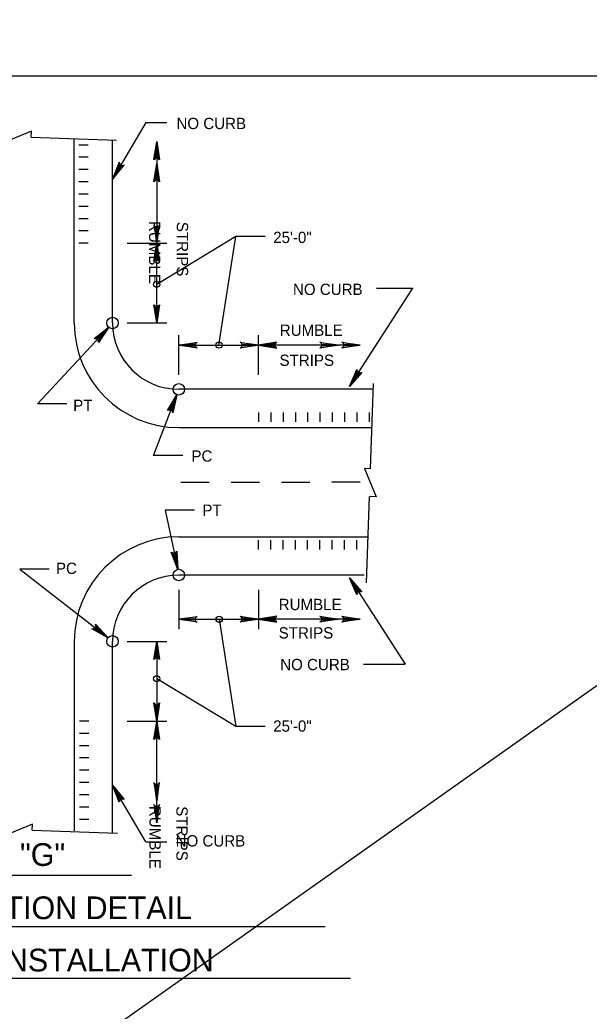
# Model space of a CAD drawing. Extents: x 632008 to 634206, y 294231 to 297795.
# Drawn here: x 633738.6 to 633889.8, y 295155.4 to 295418.6 of the extents above; entities that cross this region are included whole.
import ezdxf

# ---------------------------------------------------------------- set-up
doc = ezdxf.new("R2010")
doc.units = 0
for name, color, linetype in [('1', 7, 'Continuous'), ('2', 7, 'Continuous'), ('3', 7, 'Continuous'), ('Level 2', 7, 'Continuous')]:
    doc.layers.add(name, color=color, linetype=linetype)

msp = doc.modelspace()

# ---------------------------------------------------------------- linework, layer by layer
at = {"layer": '1'}
for p, q in [((633753.07, 295338.13), (633753.07, 295387.09)), ((633763.23, 295338.13), (633763.23, 295386.54)), ((633756.79, 295385.38), (633754.27, 295385.38)), ((633756.79, 295382.12), (633754.27, 295382.12)), ((633756.79, 295378.86), (633754.27, 295378.86)), ((633756.79, 295375.6), (633754.27, 295375.6)), ((633756.79, 295372.34), (633754.27, 295372.34)), ((633756.79, 295369.08), (633754.27, 295369.08)), ((633756.79, 295365.82), (633754.27, 295365.82)), ((633756.79, 295362.56), (633754.27, 295362.56)), ((633795.96, 295361.09), (633774.96, 295348.37)), ((633791.5, 295332.25), (633795.96, 295361.09)), ((633756.79, 295359.29), (633754.27, 295359.29)), ((633832.49, 295320.52), (633780.84, 295320.52)), ((633802, 295314.39), (633802, 295311.88)), ((633805.27, 295314.39), (633805.27, 295311.88)), ((633808.53, 295314.39), (633808.53, 295311.88)), ((633811.79, 295314.39), (633811.79, 295311.88)), ((633815.05, 295314.39), (633815.05, 295311.88)), ((633818.31, 295314.39), (633818.31, 295311.88)), ((633821.57, 295314.39), (633821.57, 295311.88)), ((633824.83, 295314.39), (633824.83, 295311.88)), ((633828.1, 295314.39), (633828.1, 295311.88)), ((633831.36, 295314.39), (633831.36, 295311.88)), ((633780.84, 295310.36), (633832.13, 295310.36)), ((633780.84, 295281.37), (633831.12, 295281.37)), ((633802, 295277.96), (633802, 295280.48)), ((633805.27, 295277.96), (633805.27, 295280.48)), ((633808.53, 295277.96), (633808.53, 295280.48)), ((633811.79, 295277.96), (633811.79, 295280.48)), ((633815.05, 295277.96), (633815.05, 295280.48)), ((633818.31, 295277.96), (633818.31, 295280.48)), ((633821.57, 295277.96), (633821.57, 295280.48)), ((633824.83, 295277.96), (633824.83, 295280.48)), ((633828.1, 295277.96), (633828.1, 295280.48)), ((633830.05, 295271.21), (633780.84, 295271.21)), ((633791.55, 295259.48), (633795.96, 295230.97)), ((633753.07, 295253.6), (633753.07, 295203.27)), ((633763.23, 295202.72), (633763.23, 295253.6)), ((633795.96, 295230.97), (633774.96, 295243.69)), ((633756.97, 295232.44), (633754.45, 295232.44)), ((633756.97, 295229.18), (633754.45, 295229.18)), ((633756.97, 295225.91), (633754.45, 295225.91)), ((633756.97, 295222.65), (633754.45, 295222.65)), ((633756.97, 295219.39), (633754.45, 295219.39)), ((633756.97, 295216.13), (633754.45, 295216.13)), ((633756.97, 295212.87), (633754.45, 295212.87)), ((633756.97, 295209.61), (633754.45, 295209.61)), ((633756.97, 295206.35), (633754.45, 295206.35)), ((633705.11, 295191.51), (633768.25, 295191.51))]:
    msp.add_line(p, q, dxfattribs=at)
msp.add_lwpolyline([(634127.07, 294839.62), (634127.07, 295403.62), (633341.07, 295403.62), (633341.07, 294839.62), (634127.07, 294839.62), (634127.07, 294865.98), (633927.07, 294865.98), (633927.07, 294930.66), (634127.07, 294930.66), (634127.07, 294959.62), (633927.07, 294959.62), (633927.07, 294839.62), (634005.87, 294839.62), (634005.87, 294865.98), (634005.87, 294839.62), (634082.87, 294839.62), (634082.87, 294865.98), (634082.87, 294853.66), (634127.07, 294853.66)], dxfattribs=at)
msp.add_lwpolyline([(634127.07, 294839.62), (634127.07, 295403.62), (633341.07, 295403.62), (633341.07, 294839.62), (634127.07, 294839.62), (634127.07, 294865.98), (633927.07, 294865.98), (633927.07, 294930.66), (634127.07, 294930.66), (634127.07, 294959.62), (633927.07, 294959.62), (633927.07, 294839.62), (634005.87, 294839.62), (634005.87, 294865.98), (634005.87, 294839.62), (634082.87, 294839.62), (634082.87, 294865.98), (634082.87, 294853.66), (634127.07, 294853.66)], dxfattribs=at)
msp.add_lwpolyline([(634127.07, 294839.62), (634127.07, 295403.62), (633341.07, 295403.62), (633341.07, 294839.62), (634127.07, 294839.62), (634127.07, 294865.98), (633927.07, 294865.98), (633927.07, 294930.66), (634127.07, 294930.66), (634127.07, 294959.62), (633927.07, 294959.62), (633927.07, 294839.62), (634005.87, 294839.62), (634005.87, 294865.98), (634005.87, 294839.62), (634082.87, 294839.62), (634082.87, 294865.98), (634082.87, 294853.66), (634127.07, 294853.66)], dxfattribs=at)
msp.add_lwpolyline([(634127.07, 294839.62), (634127.07, 295403.62), (633341.07, 295403.62), (633341.07, 294839.62), (634127.07, 294839.62), (634127.07, 294865.98), (633927.07, 294865.98), (633927.07, 294930.66), (634127.07, 294930.66), (634127.07, 294959.62), (633927.07, 294959.62), (633927.07, 294839.62), (634005.87, 294839.62), (634005.87, 294865.98), (634005.87, 294839.62), (634082.87, 294839.62), (634082.87, 294865.98), (634082.87, 294853.66), (634127.07, 294853.66)], dxfattribs=at)
msp.add_lwpolyline([(634127.07, 294839.62), (634127.07, 295403.62), (633341.07, 295403.62), (633341.07, 294839.62), (634127.07, 294839.62), (634127.07, 294865.98), (633927.07, 294865.98), (633927.07, 294930.66), (634127.07, 294930.66), (634127.07, 294959.62), (633927.07, 294959.62), (633927.07, 294839.62), (634005.87, 294839.62), (634005.87, 294865.98), (634005.87, 294839.62), (634082.87, 294839.62), (634082.87, 294865.98), (634082.87, 294853.66), (634127.07, 294853.66)], dxfattribs=at)
for centre in [(633774.96, 295348.37), (633791.5, 295332.25), (633791.55, 295259.48), (633774.96, 295243.69)]:
    msp.add_circle(centre, 0.821, dxfattribs=at)
for centre, radius, start, end in [((633780.84, 295338.13), 27.77, 180, 270), ((633780.84, 295338.13), 17.61, 180, 270), ((633780.84, 295253.6), 27.77, 90, 180), ((633780.84, 295253.6), 17.61, 90, 180)]:
    msp.add_arc(centre, radius, start, end, dxfattribs=at)
at = {"layer": '2'}
for p, q in [((633741.71, 295389.09), (633734.21, 295385.95)), ((633741.65, 295387.49), (633741.71, 295389.09)), ((633741.65, 295387.49), (633764.26, 295386.7)), ((633831.75, 295299.45), (633832.54, 295322.06)), ((633830.15, 295299.51), (633833.29, 295292.01)), ((633831.75, 295299.45), (633830.15, 295299.51)), ((633830.69, 295269.12), (633831.49, 295292.07)), ((633833.29, 295292.01), (633831.69, 295292.07)), ((633741.97, 295205.07), (633734.47, 295201.93)), ((633741.91, 295203.47), (633741.97, 295205.07)), ((633741.91, 295203.47), (633764.52, 295202.68)), ((633656.2, 295177.87), (633819.72, 295177.87)), ((633648.82, 295164.16), (633826.43, 295164.16))]:
    msp.add_line(p, q, dxfattribs=at)
at = {"layer": '3'}
for p, q in [((633772.04, 295391.33), (633763.23, 295376.28)), ((633772.04, 295391.33), (633777.67, 295391.33)), ((633774.96, 295386.28), (633774.96, 295359.29)), ((633803.76, 295361.09), (633795.96, 295361.09)), ((633767.12, 295359.29), (633777.67, 295359.29)), ((633774.96, 295338.13), (633774.96, 295359.29)), ((633826.15, 295321.3), (633842.97, 295347.34)), ((633833.36, 295347.34), (633842.97, 295347.34)), ((633762.2, 295337.02), (633743.27, 295316.67)), ((633767.12, 295338.13), (633777.67, 295338.13)), ((633780.84, 295324.41), (633780.84, 295334.9)), ((633802, 295324.41), (633802, 295334.9)), ((633780.84, 295332.25), (633802, 295332.25)), ((633828.99, 295332.25), (633802, 295332.25)), ((633774.1, 295302.91), (633780.3, 295319.1)), ((633751.08, 295316.67), (633743.27, 295316.67)), ((633781.9, 295302.91), (633774.1, 295302.91)), ((633781.37, 295295.87), (633788.91, 295295.87)), ((633794.73, 295295.87), (633802.27, 295295.87)), ((633808.09, 295295.87), (633815.63, 295295.87)), ((633828.99, 295295.87), (633821.45, 295295.87)), ((633777.18, 295288.44), (633780.53, 295272.7)), ((633784.98, 295288.44), (633777.18, 295288.44)), ((633738.63, 295272.78), (633762.03, 295254.53)), ((633746.43, 295272.78), (633738.63, 295272.78)), ((633826.15, 295270.43), (633840.91, 295247.57)), ((633780.84, 295267.32), (633780.84, 295256.83)), ((633802, 295267.32), (633802, 295256.83)), ((633780.84, 295259.48), (633802, 295259.48)), ((633828.99, 295259.48), (633802, 295259.48)), ((633767.12, 295253.6), (633777.67, 295253.6)), ((633774.96, 295253.6), (633774.96, 295232.44)), ((633829.92, 295247.57), (633840.91, 295247.57)), ((633767.12, 295232.44), (633777.67, 295232.44)), ((633774.96, 295205.45), (633774.96, 295232.44)), ((633803.76, 295230.97), (633795.96, 295230.97)), ((633772.04, 295200.4), (633763.23, 295215.45)), ((633772.04, 295200.4), (633777.67, 295200.4))]:
    msp.add_line(p, q, dxfattribs=at)
for points in [[(633774.38, 295381.67), (633774.72, 295381.85), (633774.96, 295386.28), (633774.38, 295381.67), (633774.18, 295381.44), (633774.96, 295386.28), (633775.18, 295381.85), (633775.51, 295381.69), (633774.96, 295386.28), (633775.73, 295381.44), (633775.51, 295381.69)], [(633765.06, 295380.55), (633765.26, 295380.23), (633763.23, 295376.28), (633765.06, 295380.55), (633765, 295380.85), (633763.23, 295376.28), (633765.66, 295379.99), (633766.02, 295379.97), (633763.23, 295376.28), (633766.34, 295380.07), (633766.02, 295379.97)], [(633774.38, 295375.85), (633774.72, 295376.02), (633774.96, 295380.46), (633774.38, 295375.85), (633774.18, 295375.61), (633774.96, 295380.46), (633775.18, 295376.03), (633775.51, 295375.86), (633774.96, 295380.46), (633775.73, 295375.61), (633775.51, 295375.86)], [(633774.38, 295363.9), (633774.72, 295363.73), (633774.96, 295359.29), (633774.38, 295363.9), (633774.18, 295364.14), (633774.96, 295359.29), (633775.18, 295363.73), (633775.51, 295363.89), (633774.96, 295359.29), (633775.73, 295364.14), (633775.51, 295363.89)], [(633774.38, 295354.69), (633774.72, 295354.86), (633774.96, 295359.29), (633774.38, 295354.69), (633774.18, 295354.45), (633774.96, 295359.29), (633775.18, 295354.86), (633775.51, 295354.7), (633774.96, 295359.29), (633775.73, 295354.45), (633775.51, 295354.7)], [(633775.54, 295342.74), (633775.2, 295342.57), (633774.96, 295338.13), (633775.54, 295342.74), (633775.74, 295342.98), (633774.96, 295338.13), (633774.74, 295342.56), (633774.41, 295342.72), (633774.96, 295338.13), (633774.19, 295342.98), (633774.41, 295342.72)], [(633758.64, 295334.04), (633759, 295333.94), (633762.2, 295337.02), (633758.64, 295334.04), (633758.33, 295334.01), (633762.2, 295337.02), (633759.34, 295333.63), (633759.47, 295333.28), (633762.2, 295337.02), (633759.46, 295332.95), (633759.47, 295333.28)], [(633785.45, 295331.67), (633785.28, 295332), (633780.84, 295332.25), (633785.45, 295331.67), (633785.69, 295331.47), (633780.84, 295332.25), (633785.28, 295332.47), (633785.44, 295332.8), (633780.84, 295332.25), (633785.69, 295333.02), (633785.44, 295332.8)], [(633797.4, 295332.83), (633797.57, 295332.49), (633802, 295332.25), (633797.4, 295332.83), (633797.16, 295333.03), (633802, 295332.25), (633797.57, 295332.03), (633797.41, 295331.7), (633802, 295332.25), (633797.16, 295331.48), (633797.41, 295331.7)], [(633806.61, 295332.83), (633806.44, 295332.49), (633802, 295332.25), (633806.61, 295332.83), (633806.85, 295333.03), (633802, 295332.25), (633806.44, 295332.03), (633806.6, 295331.7), (633802, 295332.25), (633806.85, 295331.48), (633806.6, 295331.7)], [(633818.56, 295332.83), (633818.73, 295332.49), (633823.17, 295332.25), (633818.56, 295332.83), (633818.32, 295333.03), (633823.17, 295332.25), (633818.74, 295332.03), (633818.57, 295331.7), (633823.17, 295332.25), (633818.32, 295331.48), (633818.57, 295331.7)], [(633824.38, 295332.83), (633824.56, 295332.49), (633828.99, 295332.25), (633824.38, 295332.83), (633824.15, 295333.03), (633828.99, 295332.25), (633824.56, 295332.03), (633824.4, 295331.7), (633828.99, 295332.25), (633824.15, 295331.48), (633824.4, 295331.7)], [(633829.13, 295324.86), (633828.76, 295324.9), (633826.15, 295321.3), (633829.13, 295324.86), (633829.43, 295324.95), (633826.15, 295321.3), (633828.37, 295325.14), (633828.18, 295325.46), (633826.15, 295321.3), (633828.13, 295325.79), (633828.18, 295325.46)], [(633778.11, 295315.01), (633778.48, 295315.05), (633780.3, 295319.1), (633778.11, 295315.01), (633777.84, 295314.86), (633780.3, 295319.1), (633778.92, 295314.89), (633779.17, 295314.62), (633780.3, 295319.1), (633779.28, 295314.31), (633779.17, 295314.62)], [(633780.13, 295277.32), (633779.84, 295277.08), (633780.53, 295272.7), (633780.13, 295277.32), (633780.28, 295277.59), (633780.53, 295272.7), (633779.39, 295276.98), (633779.03, 295277.07), (633780.53, 295272.7), (633778.76, 295277.27), (633779.03, 295277.07)], [(633828.16, 295266.25), (633828.35, 295266.57), (633826.15, 295270.43), (633828.16, 295266.25), (633828.12, 295265.94), (633826.15, 295270.43), (633828.74, 295266.83), (633829.1, 295266.87), (633826.15, 295270.43), (633829.42, 295266.78), (633829.1, 295266.87)], [(633785.45, 295258.9), (633785.28, 295259.24), (633780.84, 295259.48), (633785.45, 295258.9), (633785.69, 295258.7), (633780.84, 295259.48), (633785.28, 295259.7), (633785.44, 295260.03), (633780.84, 295259.48), (633785.69, 295260.25), (633785.44, 295260.03)], [(633797.4, 295260.06), (633797.57, 295259.73), (633802, 295259.48), (633797.4, 295260.06), (633797.16, 295260.26), (633802, 295259.48), (633797.57, 295259.26), (633797.41, 295258.93), (633802, 295259.48), (633797.16, 295258.71), (633797.41, 295258.93)], [(633806.61, 295260.06), (633806.44, 295259.73), (633802, 295259.48), (633806.61, 295260.06), (633806.85, 295260.26), (633802, 295259.48), (633806.44, 295259.26), (633806.6, 295258.93), (633802, 295259.48), (633806.85, 295258.71), (633806.6, 295258.93)], [(633818.56, 295260.06), (633818.73, 295259.73), (633823.17, 295259.48), (633818.56, 295260.06), (633818.32, 295260.26), (633823.17, 295259.48), (633818.74, 295259.26), (633818.57, 295258.93), (633823.17, 295259.48), (633818.32, 295258.71), (633818.57, 295258.93)], [(633824.38, 295260.06), (633824.56, 295259.73), (633828.99, 295259.48), (633824.38, 295260.06), (633824.15, 295260.26), (633828.99, 295259.48), (633824.56, 295259.26), (633824.4, 295258.93), (633828.99, 295259.48), (633824.15, 295258.71), (633824.4, 295258.93)], [(633758.76, 295257.82), (633758.69, 295257.45), (633762.03, 295254.53), (633758.76, 295257.82), (633758.7, 295258.13), (633762.03, 295254.53), (633758.4, 295257.08), (633758.07, 295256.92), (633762.03, 295254.53), (633757.74, 295256.9), (633758.07, 295256.92)], [(633774.38, 295248.99), (633774.72, 295249.16), (633774.96, 295253.6), (633774.38, 295248.99), (633774.18, 295248.76), (633774.96, 295253.6), (633775.18, 295249.17), (633775.51, 295249.01), (633774.96, 295253.6), (633775.73, 295248.76), (633775.51, 295249.01)], [(633775.54, 295237.04), (633775.2, 295236.87), (633774.96, 295232.44), (633775.54, 295237.04), (633775.74, 295237.28), (633774.96, 295232.44), (633774.74, 295236.87), (633774.41, 295237.03), (633774.96, 295232.44), (633774.19, 295237.28), (633774.41, 295237.03)], [(633774.38, 295227.83), (633774.72, 295228), (633774.96, 295232.44), (633774.38, 295227.83), (633774.18, 295227.59), (633774.96, 295232.44), (633775.18, 295228), (633775.51, 295227.84), (633774.96, 295232.44), (633775.73, 295227.59), (633775.51, 295227.84)], [(633765.06, 295211.18), (633765.26, 295211.5), (633763.23, 295215.45), (633765.06, 295211.18), (633765, 295210.88), (633763.23, 295215.45), (633765.66, 295211.74), (633766.02, 295211.76), (633763.23, 295215.45), (633766.34, 295211.66), (633766.02, 295211.76)], [(633774.38, 295215.88), (633774.72, 295215.71), (633774.96, 295211.27), (633774.38, 295215.88), (633774.18, 295216.12), (633774.96, 295211.27), (633775.18, 295215.7), (633775.51, 295215.87), (633774.96, 295211.27), (633775.73, 295216.12), (633775.51, 295215.87)], [(633774.38, 295210.06), (633774.72, 295209.88), (633774.96, 295205.45), (633774.38, 295210.06), (633774.18, 295210.29), (633774.96, 295205.45), (633775.18, 295209.88), (633775.51, 295210.05), (633774.96, 295205.45), (633775.73, 295210.29), (633775.51, 295210.05)]]:
    msp.add_lwpolyline(points, dxfattribs=at)
for centre in [(633763.23, 295338.13), (633780.84, 295320.52), (633780.84, 295271.21), (633763.23, 295253.6)]:
    msp.add_circle(centre, 1.52, dxfattribs=at)
at = {"layer": 'Level 2'}
msp.add_line((633301.07, 294824.62), (634142.07, 295418.62), dxfattribs=at)

# ---------------------------------------------------------------- texts
at = {"layer": '1'}
for s, height, p in [('DETAIL "G"', 6.039, (633708.13, 295193.98)), ('TYPICAL INTERSECTION DETAIL', 6.0395, (633657.79, 295179.85)), ('FOR RUMBLE STRIP INSTALLATION', 6.0395, (633651.44, 295165.96))]:
    msp.add_text(s, height=height, dxfattribs=at).set_placement(p)
at = {"layer": '3'}
for s, p in [('NO CURB', (633780.2, 295389.61)), ('NO CURB', (633811.15, 295345.57)), ('RUMBLE', (633807.65, 295334.71)), ('STRIPS', (633807.58, 295326.74)), ('PT', (633752.78, 295314.77)), ('PC', (633784.18, 295301.31)), ('PT', (633787.08, 295286.93)), ('PC', (633748.2, 295271.5)), ('RUMBLE', (633807.36, 295261.9)), ('STRIPS', (633807.36, 295254.36)), ('NO CURB', (633779.98, 295199.14))]:
    msp.add_text(s, height=3, dxfattribs=at).set_placement(p)
for s, rotation, p in [('RUMBLE', 270, (633772.91, 295365.22)), ('STRIPS', 270, (633780.3, 295364.98)), ('25\'-0"', 360, (633805.9, 295359.36)), ('NO CURB', 360, (633807.76, 295245.95)), ('25\'-0"', 360, (633805.9, 295229.62)), ('RUMBLE', 270, (633773.03, 295209.93)), ('STRIPS', 270, (633780.19, 295209.83))]:
    msp.add_text(s, height=3, rotation=rotation, dxfattribs=at).set_placement(p)

doc.saveas('drawing.dxf')
